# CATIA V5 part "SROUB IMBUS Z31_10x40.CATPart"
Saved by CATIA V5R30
Part number: SROUB IMBUS Z31/10x40
Bounding box of the stored display mesh (mm): x -10 to 40, y -8 to 8, z -8 to 8
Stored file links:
  C:\Users\ondra\Desktop\PŘÍLOHA P III\CATIA\SROUB IMBUS Z31_10x40.CATPart
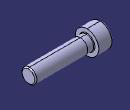
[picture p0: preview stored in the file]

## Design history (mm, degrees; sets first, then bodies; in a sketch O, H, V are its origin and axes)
Set1
  DatumSurface1 to DatumSurface30 "Z31/10x4"
  Join1: Elements (DatumSurface1; DatumSurface2; DatumSurface3; DatumSurface4; DatumSurface5; DatumSurface6; DatumSurface7; DatumSurface8; DatumSurface9; DatumSurface10; DatumSurface11; DatumSurface12; DatumSurface13; DatumSurface14; DatumSurface16; DatumSurface17; DatumSurface18; DatumSurface19; DatumSurface20; DatumSurface21; DatumSurface22; DatumSurface23; DatumSurface24; DatumSurface25; DatumSurface26; DatumSurface27; DatumSurface28; DatumSurface29; DatumSurface30)
Body1 (main body)
  CloseSurface1: CloseElement Join1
